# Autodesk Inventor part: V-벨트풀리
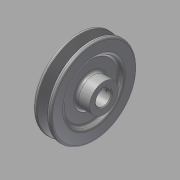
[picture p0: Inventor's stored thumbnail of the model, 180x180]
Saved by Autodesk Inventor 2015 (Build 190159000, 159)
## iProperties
Created: 2015-09
Part Number: V-벨트풀리
Material: 강철, 연강
Document SubType Name: Modeling
Designer: mduedu
Density: 7.86 g/cm^3
Mass: 779.014 g
Surface Area: 277.465 cm^2
Volume: 99.1112 cm^3
Appearance: 강철
Author: mduedu
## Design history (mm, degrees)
sketch "스케치1"
  geometry: L1 (-10, 0)-(10, 0); L2 (-10, 0)-(-10, 48); L3 (-10, 48)-(-5.976, 48); L4 (-5.976, 48)-(-2.154, 35.5); L5 (-2.154, 35.5)-(2.154, 35.5); L6 (2.154, 35.5)-(5.976, 48); L7 (5.976, 48)-(10, 48); L8 (10, 48)-(10, 0); L9 (0, 0)-(0, 35.5); L10 (-10, 43.5)-(10, 43.5); 3 further points
  constraints: 20 end point, 6 point on line, 3 perpendicular, 2 midpoint, 2 parallel, 2 symmetric about line, 1 coincident, 1 collinear, 1 equal length, 1 horizontal, 1 vertical, 1 vertical alignment
  dimensions: "d0" = 20 distance between parallel lines of L8 L2; "d2" = 96 diameter of L3 L1; "d3" = 87 diameter of L10 L1; "d4" = 4.5 distance between parallel lines of L10 L3 (derived); "d5" = 8 distance between parallel lines of L5 L10; "d6" = 9.2 distance of point (4.6, 43.5) point (-4.6, 43.5); "d7" = 34 deg angle of L6 L4
revolve "회전1" sketch "스케치1" stored, may be unused: angle "d8" = 90 deg
sketch "스케치2"
  geometry: C1 r 16 at (0, 0); 1 further point
  constraints: 1 centre point, 1 coincident
  dimensions: "d9" = 32 diameter of C1
extrude "돌출1" join sketch "스케치2" distance "d10" = 11; taper "d11" = 0 deg
fillet "모깎기1" dims "d12" = 1, "d13" = 0.5, "d14" = 2
sketch "스케치3"
  geometry: C1 r 16 at (0, 0) reference; C2 r 32 at (0, 0); 1 further point
  constraints: 1 centre point, 1 coincident
  dimensions: "d15" = 64 diameter of C2
extrude "돌출2" cut sketch "스케치3" distance "d16" = 4; taper "d17" = 0 deg
fillet "모깎기2" dims "d18" = 3
fillet "모깎기3" dims "d19" = 3
fillet "모깎기4" dims "d20" = 3
sketch "스케치4"
  geometry: C1 r 8.5 at (0, 0); 1 further point
  constraints: 1 centre point, 1 coincident
  dimensions: "d21" = 17 diameter of C1
extrude "돌출3" cut sketch "스케치4" stored distance "d22" = 4; taper "d23" = 0 deg
sketch "스케치5"
  geometry: L1 (-2.5, 8.124)-(2.5, 8.124); L2 (2.5, 8.124)-(2.5, 10.8); L3 (2.5, 10.8)-(-2.5, 10.8); L4 (-2.5, 10.8)-(-2.5, 8.124); A1 r 8.5 centre (0, 0) between (-2.5, 8.124) and (2.5, 8.124) reference; 2 further points
  constraints: 8 end point, 3 point on circle, 2 parallel, 1 horizontal, 1 perpendicular, 1 vertical alignment
  dimensions: "d24" = 5 distance of L2.end L3.end; "d26" = 19.3 distance from line of L3 point (0, -8.5)
extrude "돌출4" cut sketch "스케치5" stored distance "d27" = 4; taper "d28" = 0 deg
chamfer "모따기1" distance "d29" = 1; stored, may be unused: second distance "d30" = 2, angle "d31" = 45 deg
node "작업 평면1"
sketch "스케치6"
  geometry: L1 (-11, 16)-(-11, -16) reference; 2 further points
  constraints: 1 horizontal alignment
  dimensions: "d32" = 5 distance from line of point (-6, 0) L1
hole "구멍1" sketch "스케치6" at (-6, 0) diameter "d33" = 3.242; stored, may be unused: countersink angle "d37" = 90 deg, drill point angle "d39" = 118 deg; dims "d34" = 6, "d35" = 4, "d36" = 2, "d38" = 8
node "솔리드1"
mirror "대칭1"
